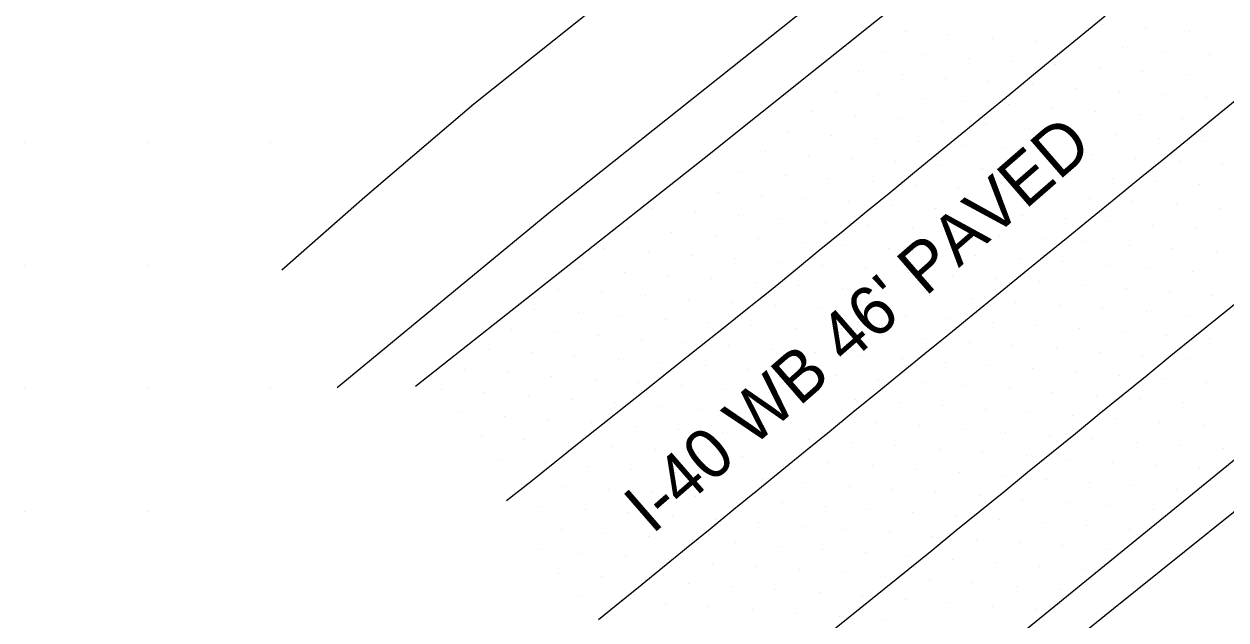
# Model space of a CAD drawing. Extents: x 1548934 to 1561348, y 809680 to 824075.
# Drawn here: x 1551360 to 1551457.5, y 810431.2 to 810479.5 of the extents above; entities that cross this region are included whole.
import ezdxf

# ---------------------------------------------------------------- set-up
doc = ezdxf.new("R2010")
doc.units = 0
for name, color, linetype in [('E_NCDOT_Vertical_Profile_Ground_Line', 7, 'Continuous'), ('Exist DTM QL2 LIDAR Elevation Point', 7, 'Continuous'), ('Exist DTM Scan Elevation Point', 7, 'Continuous'), ('Exist Roads EOP Text', 7, 'Continuous'), ('P_RDY_Terminator_Cell', 7, 'Continuous'), ('PH Exist DTM Breakline', 7, 'Continuous')]:
    doc.layers.add(name, color=color, linetype=linetype)

msp = doc.modelspace()

# ---------------------------------------------------------------- linework, layer by layer
at = {"layer": 'E_NCDOT_Vertical_Profile_Ground_Line'}
for points in [[(1551391.748, 810450.158), (1551415.179, 810468.674), (1551438.587, 810487.393), (1551461.862, 810506.256), (1551485.056, 810525.284), (1551508.262, 810544.296), (1551531.347, 810563.293), (1551554.369, 810582.488), (1551577.415, 810601.694), (1551600.296, 810621.053), (1551623.114, 810640.529), (1551645.931, 810660.005)], [(1551420.508, 810413.559), (1551431.924, 810422.797), (1551455.236, 810441.768), (1551478.523, 810460.78), (1551501.702, 810479.825), (1551524.839, 810499.022), (1551547.879, 810518.234), (1551570.873, 810537.502), (1551593.819, 810556.903), (1551616.71, 810576.292), (1551639.811, 810595.486)]]:
    msp.add_lwpolyline(points, dxfattribs=at)
at = {"layer": 'Exist DTM QL2 LIDAR Elevation Point'}
for p, q in [((1551359.968, 810469.969), (1551359.968, 810469.969)), ((1551369.969, 810469.969), (1551369.969, 810469.969)), ((1551379.969, 810469.969), (1551379.969, 810469.969)), ((1551359.968, 810459.968), (1551359.968, 810459.968)), ((1551369.969, 810459.968), (1551369.969, 810459.968)), ((1551359.968, 810449.967), (1551359.968, 810449.967)), ((1551369.969, 810449.967), (1551369.969, 810449.967)), ((1551379.969, 810449.967), (1551379.969, 810449.967)), ((1551359.968, 810439.966), (1551359.968, 810439.966)), ((1551369.969, 810439.966), (1551369.969, 810439.966))]:
    msp.add_line(p, q, dxfattribs=at)
at = {"layer": 'Exist DTM Scan Elevation Point'}
for p, q in [((1551431.502, 810478.948), (1551431.502, 810478.948)), ((1551447.498, 810479.506), (1551447.498, 810479.506)), ((1551451.024, 810479.238), (1551451.024, 810479.238)), ((1551454.549, 810478.97), (1551454.549, 810478.97)), ((1551435.027, 810478.68), (1551435.027, 810478.68)), ((1551438.552, 810478.412), (1551438.552, 810478.412)), ((1551442.077, 810478.144), (1551442.077, 810478.144)), ((1551445.602, 810477.877), (1551445.602, 810477.877)), ((1551429.606, 810477.319), (1551429.606, 810477.319)), ((1551433.131, 810477.051), (1551433.131, 810477.051)), ((1551436.656, 810476.783), (1551436.656, 810476.783)), ((1551449.127, 810477.609), (1551449.127, 810477.609)), ((1551452.652, 810477.341), (1551452.652, 810477.341)), ((1551456.178, 810477.074), (1551456.178, 810477.074)), ((1551440.181, 810476.516), (1551440.181, 810476.516)), ((1551443.706, 810476.248), (1551443.706, 810476.248)), ((1551447.231, 810475.98), (1551447.231, 810475.98)), ((1551427.71, 810475.69), (1551427.71, 810475.69)), ((1551431.235, 810475.422), (1551431.235, 810475.422)), ((1551434.759, 810475.155), (1551434.759, 810475.155)), ((1551438.284, 810474.887), (1551438.284, 810474.887)), ((1551450.756, 810475.713), (1551450.756, 810475.713)), ((1551454.281, 810475.445), (1551454.281, 810475.445)), ((1551425.813, 810474.062), (1551425.813, 810474.062)), ((1551441.809, 810474.619), (1551441.809, 810474.619)), ((1551445.334, 810474.351), (1551445.334, 810474.351)), ((1551448.86, 810474.084), (1551448.86, 810474.084)), ((1551452.385, 810473.816), (1551452.385, 810473.816)), ((1551429.338, 810473.794), (1551429.338, 810473.794)), ((1551432.863, 810473.526), (1551432.863, 810473.526)), ((1551436.388, 810473.258), (1551436.388, 810473.258)), ((1551439.913, 810472.99), (1551439.913, 810472.99)), ((1551455.91, 810473.548), (1551455.91, 810473.548)), ((1551423.917, 810472.433), (1551423.917, 810472.433)), ((1551427.442, 810472.165), (1551427.442, 810472.165)), ((1551430.967, 810471.897), (1551430.967, 810471.897)), ((1551443.438, 810472.722), (1551443.438, 810472.722)), ((1551446.963, 810472.455), (1551446.963, 810472.455)), ((1551450.489, 810472.187), (1551450.489, 810472.187)), ((1551454.014, 810471.92), (1551454.014, 810471.92)), ((1551434.492, 810471.629), (1551434.492, 810471.629)), ((1551438.017, 810471.361), (1551438.017, 810471.361)), ((1551441.542, 810471.093), (1551441.542, 810471.093)), ((1551422.021, 810470.804), (1551422.021, 810470.804)), ((1551425.545, 810470.536), (1551425.545, 810470.536)), ((1551429.07, 810470.268), (1551429.07, 810470.268)), ((1551432.595, 810470), (1551432.595, 810470)), ((1551445.067, 810470.826), (1551445.067, 810470.826)), ((1551448.592, 810470.558), (1551448.592, 810470.558)), ((1551452.117, 810470.291), (1551452.117, 810470.291)), ((1551455.643, 810470.023), (1551455.643, 810470.023)), ((1551420.124, 810469.175), (1551420.124, 810469.175)), ((1551436.12, 810469.732), (1551436.12, 810469.732)), ((1551439.645, 810469.464), (1551439.645, 810469.464)), ((1551443.171, 810469.197), (1551443.171, 810469.197)), ((1551423.649, 810468.907), (1551423.649, 810468.907)), ((1551427.174, 810468.639), (1551427.174, 810468.639)), ((1551430.699, 810468.371), (1551430.699, 810468.371)), ((1551434.224, 810468.103), (1551434.224, 810468.103)), ((1551446.696, 810468.929), (1551446.696, 810468.929)), ((1551450.221, 810468.662), (1551450.221, 810468.662)), ((1551453.746, 810468.394), (1551453.746, 810468.394)), ((1551457.272, 810468.126), (1551457.272, 810468.126)), ((1551418.228, 810467.546), (1551418.228, 810467.546)), ((1551421.752, 810467.278), (1551421.752, 810467.278)), ((1551425.277, 810467.01), (1551425.277, 810467.01)), ((1551437.749, 810467.836), (1551437.749, 810467.836)), ((1551441.274, 810467.568), (1551441.274, 810467.568)), ((1551444.799, 810467.3), (1551444.799, 810467.3)), ((1551448.325, 810467.033), (1551448.325, 810467.033)), ((1551428.802, 810466.742), (1551428.802, 810466.742)), ((1551432.327, 810466.474), (1551432.327, 810466.474)), ((1551435.853, 810466.207), (1551435.853, 810466.207)), ((1551451.85, 810466.765), (1551451.85, 810466.765)), ((1551455.375, 810466.497), (1551455.375, 810466.497)), ((1551416.331, 810465.917), (1551416.331, 810465.917)), ((1551419.856, 810465.649), (1551419.856, 810465.649)), ((1551423.381, 810465.381), (1551423.381, 810465.381)), ((1551426.906, 810465.113), (1551426.906, 810465.113)), ((1551439.378, 810465.939), (1551439.378, 810465.939)), ((1551442.903, 810465.671), (1551442.903, 810465.671)), ((1551446.428, 810465.404), (1551446.428, 810465.404)), ((1551449.954, 810465.136), (1551449.954, 810465.136)), ((1551410.91, 810464.556), (1551410.91, 810464.556)), ((1551414.435, 810464.288), (1551414.435, 810464.288)), ((1551430.431, 810464.845), (1551430.431, 810464.845)), ((1551433.956, 810464.578), (1551433.956, 810464.578)), ((1551437.481, 810464.31), (1551437.481, 810464.31)), ((1551453.479, 810464.869), (1551453.479, 810464.869)), ((1551457.004, 810464.601), (1551457.004, 810464.601)), ((1551417.96, 810464.02), (1551417.96, 810464.02)), ((1551421.485, 810463.752), (1551421.485, 810463.752)), ((1551425.01, 810463.484), (1551425.01, 810463.484)), ((1551428.535, 810463.216), (1551428.535, 810463.216)), ((1551441.007, 810464.042), (1551441.007, 810464.042)), ((1551444.532, 810463.775), (1551444.532, 810463.775)), ((1551448.057, 810463.507), (1551448.057, 810463.507)), ((1551451.582, 810463.24), (1551451.582, 810463.24)), ((1551409.014, 810462.927), (1551409.014, 810462.927)), ((1551412.538, 810462.659), (1551412.538, 810462.659)), ((1551416.063, 810462.391), (1551416.063, 810462.391)), ((1551419.588, 810462.123), (1551419.588, 810462.123)), ((1551432.06, 810462.949), (1551432.06, 810462.949)), ((1551435.585, 810462.681), (1551435.585, 810462.681)), ((1551439.11, 810462.414), (1551439.11, 810462.414)), ((1551442.636, 810462.146), (1551442.636, 810462.146)), ((1551455.107, 810462.972), (1551455.107, 810462.972)), ((1551407.117, 810461.298), (1551407.117, 810461.298)), ((1551423.113, 810461.855), (1551423.113, 810461.855)), ((1551426.638, 810461.587), (1551426.638, 810461.587)), ((1551430.163, 810461.32), (1551430.163, 810461.32)), ((1551446.161, 810461.878), (1551446.161, 810461.878)), ((1551449.686, 810461.611), (1551449.686, 810461.611)), ((1551453.211, 810461.343), (1551453.211, 810461.343)), ((1551410.642, 810461.03), (1551410.642, 810461.03)), ((1551414.167, 810460.762), (1551414.167, 810460.762)), ((1551417.692, 810460.494), (1551417.692, 810460.494)), ((1551421.217, 810460.226), (1551421.217, 810460.226)), ((1551433.689, 810461.052), (1551433.689, 810461.052)), ((1551437.214, 810460.785), (1551437.214, 810460.785)), ((1551440.739, 810460.517), (1551440.739, 810460.517)), ((1551444.264, 810460.249), (1551444.264, 810460.249)), ((1551456.736, 810461.075), (1551456.736, 810461.075)), ((1551405.22, 810459.668), (1551405.22, 810459.668)), ((1551408.745, 810459.401), (1551408.745, 810459.401)), ((1551424.742, 810459.959), (1551424.742, 810459.959)), ((1551428.267, 810459.691), (1551428.267, 810459.691)), ((1551431.792, 810459.423), (1551431.792, 810459.423)), ((1551447.789, 810459.982), (1551447.789, 810459.982)), ((1551451.315, 810459.714), (1551451.315, 810459.714)), ((1551454.84, 810459.446), (1551454.84, 810459.446)), ((1551412.27, 810459.133), (1551412.27, 810459.133)), ((1551415.795, 810458.865), (1551415.795, 810458.865)), ((1551419.32, 810458.597), (1551419.32, 810458.597)), ((1551422.845, 810458.33), (1551422.845, 810458.33)), ((1551435.318, 810459.156), (1551435.318, 810459.156)), ((1551438.843, 810458.888), (1551438.843, 810458.888)), ((1551442.368, 810458.62), (1551442.368, 810458.62)), ((1551445.893, 810458.353), (1551445.893, 810458.353)), ((1551403.323, 810458.039), (1551403.323, 810458.039)), ((1551406.848, 810457.771), (1551406.848, 810457.771)), ((1551410.374, 810457.504), (1551410.374, 810457.504)), ((1551413.899, 810457.236), (1551413.899, 810457.236)), ((1551426.371, 810458.062), (1551426.371, 810458.062)), ((1551429.896, 810457.794), (1551429.896, 810457.794)), ((1551433.421, 810457.527), (1551433.421, 810457.527)), ((1551436.946, 810457.259), (1551436.946, 810457.259)), ((1551449.418, 810458.085), (1551449.418, 810458.085)), ((1551452.943, 810457.817), (1551452.943, 810457.817)), ((1551456.469, 810457.55), (1551456.469, 810457.55)), ((1551401.427, 810456.411), (1551401.427, 810456.411)), ((1551417.424, 810456.968), (1551417.424, 810456.968)), ((1551420.949, 810456.701), (1551420.949, 810456.701)), ((1551424.474, 810456.433), (1551424.474, 810456.433)), ((1551440.472, 810456.991), (1551440.472, 810456.991)), ((1551443.997, 810456.724), (1551443.997, 810456.724)), ((1551447.522, 810456.456), (1551447.522, 810456.456)), ((1551404.952, 810456.142), (1551404.952, 810456.142)), ((1551408.477, 810455.875), (1551408.477, 810455.875)), ((1551412.002, 810455.607), (1551412.002, 810455.607)), ((1551415.528, 810455.34), (1551415.528, 810455.34)), ((1551428, 810456.165), (1551428, 810456.165)), ((1551431.525, 810455.898), (1551431.525, 810455.898)), ((1551435.05, 810455.63), (1551435.05, 810455.63)), ((1551438.575, 810455.363), (1551438.575, 810455.363)), ((1551451.047, 810456.189), (1551451.047, 810456.189)), ((1551454.572, 810455.921), (1551454.572, 810455.921)), ((1551399.531, 810454.781), (1551399.531, 810454.781)), ((1551403.056, 810454.514), (1551403.056, 810454.514)), ((1551419.053, 810455.072), (1551419.053, 810455.072)), ((1551422.578, 810454.804), (1551422.578, 810454.804)), ((1551426.103, 810454.536), (1551426.103, 810454.536)), ((1551442.1, 810455.095), (1551442.1, 810455.095)), ((1551445.625, 810454.827), (1551445.625, 810454.827)), ((1551449.151, 810454.56), (1551449.151, 810454.56)), ((1551406.581, 810454.246), (1551406.581, 810454.246)), ((1551410.106, 810453.978), (1551410.106, 810453.978)), ((1551413.631, 810453.71), (1551413.631, 810453.71)), ((1551417.156, 810453.443), (1551417.156, 810453.443)), ((1551429.628, 810454.269), (1551429.628, 810454.269)), ((1551433.154, 810454.001), (1551433.154, 810454.001)), ((1551436.679, 810453.734), (1551436.679, 810453.734)), ((1551440.204, 810453.466), (1551440.204, 810453.466)), ((1551452.676, 810454.292), (1551452.676, 810454.292)), ((1551456.202, 810454.025), (1551456.202, 810454.025)), ((1551397.635, 810453.153), (1551397.635, 810453.153)), ((1551401.159, 810452.885), (1551401.159, 810452.885)), ((1551404.685, 810452.617), (1551404.685, 810452.617)), ((1551408.209, 810452.349), (1551408.209, 810452.349)), ((1551420.682, 810453.175), (1551420.682, 810453.175)), ((1551424.207, 810452.908), (1551424.207, 810452.908)), ((1551427.732, 810452.64), (1551427.732, 810452.64)), ((1551431.257, 810452.372), (1551431.257, 810452.372)), ((1551443.729, 810453.198), (1551443.729, 810453.198)), ((1551447.254, 810452.931), (1551447.254, 810452.931)), ((1551450.78, 810452.663), (1551450.78, 810452.663)), ((1551454.305, 810452.396), (1551454.305, 810452.396)), ((1551395.738, 810451.523), (1551395.738, 810451.523)), ((1551411.735, 810452.081), (1551411.735, 810452.081)), ((1551415.26, 810451.814), (1551415.26, 810451.814)), ((1551418.785, 810451.546), (1551418.785, 810451.546)), ((1551434.782, 810452.105), (1551434.782, 810452.105)), ((1551438.308, 810451.837), (1551438.308, 810451.837)), ((1551441.833, 810451.569), (1551441.833, 810451.569)), ((1551399.263, 810451.256), (1551399.263, 810451.256)), ((1551402.788, 810450.988), (1551402.788, 810450.988)), ((1551406.313, 810450.72), (1551406.313, 810450.72)), ((1551409.838, 810450.452), (1551409.838, 810450.452)), ((1551422.31, 810451.279), (1551422.31, 810451.279)), ((1551425.836, 810451.011), (1551425.836, 810451.011)), ((1551429.361, 810450.743), (1551429.361, 810450.743)), ((1551432.886, 810450.476), (1551432.886, 810450.476)), ((1551445.358, 810451.302), (1551445.358, 810451.302)), ((1551448.883, 810451.034), (1551448.883, 810451.034)), ((1551452.409, 810450.767), (1551452.409, 810450.767)), ((1551455.935, 810450.5), (1551455.935, 810450.5)), ((1551393.842, 810449.894), (1551393.842, 810449.894)), ((1551397.366, 810449.626), (1551397.366, 810449.626)), ((1551413.363, 810450.185), (1551413.363, 810450.185)), ((1551416.889, 810449.917), (1551416.889, 810449.917)), ((1551420.414, 810449.65), (1551420.414, 810449.65)), ((1551436.411, 810450.208), (1551436.411, 810450.208)), ((1551439.936, 810449.94), (1551439.936, 810449.94)), ((1551443.462, 810449.673), (1551443.462, 810449.673)), ((1551400.892, 810449.359), (1551400.892, 810449.359)), ((1551404.417, 810449.091), (1551404.417, 810449.091)), ((1551407.942, 810448.824), (1551407.942, 810448.824)), ((1551411.467, 810448.556), (1551411.467, 810448.556)), ((1551423.939, 810449.382), (1551423.939, 810449.382)), ((1551427.464, 810449.114), (1551427.464, 810449.114)), ((1551430.99, 810448.847), (1551430.99, 810448.847)), ((1551434.515, 810448.579), (1551434.515, 810448.579)), ((1551446.987, 810449.405), (1551446.987, 810449.405)), ((1551450.513, 810449.138), (1551450.513, 810449.138)), ((1551454.038, 810448.871), (1551454.038, 810448.871)), ((1551395.47, 810447.998), (1551395.47, 810447.998)), ((1551398.995, 810447.73), (1551398.995, 810447.73)), ((1551414.992, 810448.288), (1551414.992, 810448.288)), ((1551418.518, 810448.021), (1551418.518, 810448.021)), ((1551422.043, 810447.753), (1551422.043, 810447.753)), ((1551425.568, 810447.486), (1551425.568, 810447.486)), ((1551438.04, 810448.311), (1551438.04, 810448.311)), ((1551441.565, 810448.044), (1551441.565, 810448.044)), ((1551445.09, 810447.776), (1551445.09, 810447.776)), ((1551448.616, 810447.509), (1551448.616, 810447.509)), ((1551402.521, 810447.462), (1551402.521, 810447.462)), ((1551406.046, 810447.195), (1551406.046, 810447.195)), ((1551409.571, 810446.927), (1551409.571, 810446.927)), ((1551413.096, 810446.659), (1551413.096, 810446.659)), ((1551429.093, 810447.218), (1551429.093, 810447.218)), ((1551432.618, 810446.95), (1551432.618, 810446.95)), ((1551436.143, 810446.682), (1551436.143, 810446.682)), ((1551452.142, 810447.242), (1551452.142, 810447.242)), ((1551455.668, 810446.975), (1551455.668, 810446.975)), ((1551397.099, 810446.101), (1551397.099, 810446.101)), ((1551400.624, 810445.833), (1551400.624, 810445.833)), ((1551404.149, 810445.566), (1551404.149, 810445.566)), ((1551416.621, 810446.392), (1551416.621, 810446.392)), ((1551420.146, 810446.124), (1551420.146, 810446.124)), ((1551423.672, 810445.857), (1551423.672, 810445.857)), ((1551427.197, 810445.589), (1551427.197, 810445.589)), ((1551439.669, 810446.415), (1551439.669, 810446.415)), ((1551443.194, 810446.147), (1551443.194, 810446.147)), ((1551446.72, 810445.88), (1551446.72, 810445.88)), ((1551450.245, 810445.613), (1551450.245, 810445.613)), ((1551407.674, 810445.298), (1551407.674, 810445.298)), ((1551411.199, 810445.03), (1551411.199, 810445.03)), ((1551414.725, 810444.763), (1551414.725, 810444.763)), ((1551430.722, 810445.321), (1551430.722, 810445.321)), ((1551434.247, 810445.054), (1551434.247, 810445.054)), ((1551437.772, 810444.786), (1551437.772, 810444.786)), ((1551453.771, 810445.346), (1551453.771, 810445.346)), ((1551457.297, 810445.079), (1551457.297, 810445.079)), ((1551398.728, 810444.204), (1551398.728, 810444.204)), ((1551402.253, 810443.937), (1551402.253, 810443.937)), ((1551405.778, 810443.669), (1551405.778, 810443.669)), ((1551418.25, 810444.495), (1551418.25, 810444.495)), ((1551421.775, 810444.228), (1551421.775, 810444.228)), ((1551425.3, 810443.96), (1551425.3, 810443.96)), ((1551428.826, 810443.692), (1551428.826, 810443.692)), ((1551441.298, 810444.518), (1551441.298, 810444.518)), ((1551444.823, 810444.251), (1551444.823, 810444.251)), ((1551448.349, 810443.984), (1551448.349, 810443.984)), ((1551451.875, 810443.717), (1551451.875, 810443.717)), ((1551409.303, 810443.401), (1551409.303, 810443.401)), ((1551412.828, 810443.134), (1551412.828, 810443.134)), ((1551416.354, 810442.866), (1551416.354, 810442.866)), ((1551419.879, 810442.599), (1551419.879, 810442.599)), ((1551432.351, 810443.425), (1551432.351, 810443.425)), ((1551435.876, 810443.157), (1551435.876, 810443.157)), ((1551439.401, 810442.889), (1551439.401, 810442.889)), ((1551442.927, 810442.622), (1551442.927, 810442.622)), ((1551455.401, 810443.45), (1551455.401, 810443.45)), ((1551400.356, 810442.308), (1551400.356, 810442.308)), ((1551403.881, 810442.04), (1551403.881, 810442.04)), ((1551407.407, 810441.773), (1551407.407, 810441.773)), ((1551423.404, 810442.331), (1551423.404, 810442.331)), ((1551426.929, 810442.063), (1551426.929, 810442.063)), ((1551430.454, 810441.796), (1551430.454, 810441.796)), ((1551446.453, 810442.355), (1551446.453, 810442.355)), ((1551449.978, 810442.088), (1551449.978, 810442.088)), ((1551453.504, 810441.821), (1551453.504, 810441.821)), ((1551410.932, 810441.505), (1551410.932, 810441.505)), ((1551414.457, 810441.237), (1551414.457, 810441.237)), ((1551417.982, 810440.97), (1551417.982, 810440.97)), ((1551421.508, 810440.702), (1551421.508, 810440.702)), ((1551433.98, 810441.528), (1551433.98, 810441.528)), ((1551437.505, 810441.261), (1551437.505, 810441.261)), ((1551441.031, 810440.993), (1551441.031, 810440.993)), ((1551444.556, 810440.726), (1551444.556, 810440.726)), ((1551401.985, 810440.411), (1551401.985, 810440.411)), ((1551405.51, 810440.143), (1551405.51, 810440.143)), ((1551409.036, 810439.876), (1551409.036, 810439.876)), ((1551425.033, 810440.434), (1551425.033, 810440.434)), ((1551428.558, 810440.167), (1551428.558, 810440.167)), ((1551432.083, 810439.899), (1551432.083, 810439.899)), ((1551448.082, 810440.459), (1551448.082, 810440.459)), ((1551451.608, 810440.192), (1551451.608, 810440.192)), ((1551412.561, 810439.608), (1551412.561, 810439.608)), ((1551416.086, 810439.341), (1551416.086, 810439.341)), ((1551419.611, 810439.073), (1551419.611, 810439.073)), ((1551423.137, 810438.806), (1551423.137, 810438.806)), ((1551435.609, 810439.632), (1551435.609, 810439.632)), ((1551439.134, 810439.364), (1551439.134, 810439.364)), ((1551442.66, 810439.097), (1551442.66, 810439.097)), ((1551446.186, 810438.83), (1551446.186, 810438.83)), ((1551403.614, 810438.515), (1551403.614, 810438.515)), ((1551407.139, 810438.247), (1551407.139, 810438.247)), ((1551410.664, 810437.979), (1551410.664, 810437.979)), ((1551426.662, 810438.538), (1551426.662, 810438.538)), ((1551430.187, 810438.27), (1551430.187, 810438.27)), ((1551433.712, 810438.003), (1551433.712, 810438.003)), ((1551437.238, 810437.736), (1551437.238, 810437.736)), ((1551449.712, 810438.563), (1551449.712, 810438.563)), ((1551401.718, 810436.886), (1551401.718, 810436.886)), ((1551414.19, 810437.712), (1551414.19, 810437.712)), ((1551417.715, 810437.444), (1551417.715, 810437.444)), ((1551421.24, 810437.177), (1551421.24, 810437.177)), ((1551424.765, 810436.909), (1551424.765, 810436.909)), ((1551440.763, 810437.468), (1551440.763, 810437.468)), ((1551444.289, 810437.201), (1551444.289, 810437.201)), ((1551447.815, 810436.934), (1551447.815, 810436.934)), ((1551405.243, 810436.618), (1551405.243, 810436.618)), ((1551408.768, 810436.35), (1551408.768, 810436.35)), ((1551412.293, 810436.083), (1551412.293, 810436.083)), ((1551415.818, 810435.815), (1551415.818, 810435.815)), ((1551428.291, 810436.641), (1551428.291, 810436.641)), ((1551431.816, 810436.374), (1551431.816, 810436.374)), ((1551435.341, 810436.107), (1551435.341, 810436.107)), ((1551438.867, 810435.839), (1551438.867, 810435.839)), ((1551403.346, 810434.989), (1551403.346, 810434.989)), ((1551419.344, 810435.548), (1551419.344, 810435.548)), ((1551422.869, 810435.28), (1551422.869, 810435.28)), ((1551426.394, 810435.013), (1551426.394, 810435.013)), ((1551442.393, 810435.572), (1551442.393, 810435.572)), ((1551445.919, 810435.305), (1551445.919, 810435.305)), ((1551406.872, 810434.722), (1551406.872, 810434.722)), ((1551410.397, 810434.454), (1551410.397, 810434.454)), ((1551413.922, 810434.186), (1551413.922, 810434.186)), ((1551417.447, 810433.919), (1551417.447, 810433.919)), ((1551429.92, 810434.745), (1551429.92, 810434.745)), ((1551433.445, 810434.478), (1551433.445, 810434.478)), ((1551436.971, 810434.21), (1551436.971, 810434.21)), ((1551440.496, 810433.943), (1551440.496, 810433.943)), ((1551404.975, 810433.093), (1551404.975, 810433.093)), ((1551420.973, 810433.651), (1551420.973, 810433.651)), ((1551424.498, 810433.384), (1551424.498, 810433.384)), ((1551428.023, 810433.116), (1551428.023, 810433.116)), ((1551431.549, 810432.849), (1551431.549, 810432.849)), ((1551444.022, 810433.676), (1551444.022, 810433.676)), ((1551408.5, 810432.825), (1551408.5, 810432.825)), ((1551412.026, 810432.557), (1551412.026, 810432.557)), ((1551415.551, 810432.29), (1551415.551, 810432.29)), ((1551419.076, 810432.022), (1551419.076, 810432.022)), ((1551435.074, 810432.581), (1551435.074, 810432.581)), ((1551438.6, 810432.314), (1551438.6, 810432.314)), ((1551442.126, 810432.047), (1551442.126, 810432.047)), ((1551422.601, 810431.755), (1551422.601, 810431.755)), ((1551426.127, 810431.487), (1551426.127, 810431.487)), ((1551429.652, 810431.22), (1551429.652, 810431.22))]:
    msp.add_line(p, q, dxfattribs=at)
at = {"layer": 'P_RDY_Terminator_Cell'}
for points in [[(1551399.137, 810440.884), (1551401.093, 810442.442), (1551403.048, 810444), (1551405.003, 810445.558), (1551406.958, 810447.116), (1551408.914, 810448.674), (1551410.869, 810450.232), (1551412.824, 810451.79), (1551414.779, 810453.347), (1551416.734, 810454.905), (1551418.69, 810456.463), (1551420.645, 810458.021), (1551422.582, 810459.601), (1551424.515, 810461.187), (1551426.448, 810462.772), (1551428.381, 810464.357), (1551430.315, 810465.942), (1551432.248, 810467.528), (1551434.181, 810469.113), (1551436.114, 810470.698), (1551438.047, 810472.284), (1551439.98, 810473.869), (1551441.913, 810475.454), (1551443.846, 810477.039), (1551445.779, 810478.625), (1551447.713, 810480.21)], [(1551458.282, 810473.323), (1551456.344, 810471.743), (1551454.406, 810470.163), (1551452.468, 810468.584), (1551450.531, 810467.004), (1551448.593, 810465.424), (1551446.655, 810463.845), (1551444.717, 810462.265), (1551442.78, 810460.686), (1551440.842, 810459.106), (1551438.904, 810457.526), (1551436.966, 810455.947), (1551435.029, 810454.367), (1551433.091, 810452.788), (1551431.153, 810451.208), (1551429.215, 810449.628), (1551427.278, 810448.049), (1551425.34, 810446.469), (1551423.402, 810444.89), (1551421.464, 810443.31), (1551419.527, 810441.73), (1551417.589, 810440.151), (1551415.651, 810438.571), (1551413.713, 810436.992), (1551411.776, 810435.412), (1551409.838, 810433.832), (1551407.9, 810432.253), (1551406.604, 810431.196)], [(1551458.895, 810457.328), (1551456.949, 810455.758), (1551455.002, 810454.189), (1551453.057, 810452.619), (1551451.118, 810451.041), (1551449.179, 810449.463), (1551447.239, 810447.886), (1551445.3, 810446.308), (1551443.361, 810444.73), (1551441.421, 810443.153), (1551439.482, 810441.575), (1551437.543, 810439.997), (1551435.604, 810438.42), (1551433.664, 810436.842), (1551431.725, 810435.264), (1551429.776, 810433.698), (1551427.828, 810432.131), (1551425.88, 810430.565), (1551423.931, 810428.998), (1551421.983, 810427.432), (1551420.035, 810425.865), (1551418.086, 810424.299), (1551416.138, 810422.732), (1551414.313, 810421.265)]]:
    msp.add_lwpolyline(points, dxfattribs=at)
at = {"layer": 'PH Exist DTM Breakline'}
for points in [[(1551623.76, 810648.551), (1551611.653, 810637.657), (1551598.616, 810624.306), (1551581.601, 810609.451), (1551566.315, 810596.609), (1551550.141, 810583.072), (1551531.518, 810567.498), (1551514.04, 810553.206), (1551494.6, 810537.72), (1551475.139, 810521.964), (1551457.515, 810507.591), (1551444.994, 810497.86), (1551424.723, 810481.845), (1551402.559, 810464.194), (1551385.382, 810450.038)], [(1551417.883, 810407.398), (1551432.392, 810419.235), (1551448.388, 810432.126), (1551463.908, 810444.556), (1551480.556, 810458.727), (1551495.998, 810470.721), (1551512.779, 810483.455), (1551526.124, 810494.877), (1551540.797, 810506.743), (1551554.488, 810518.26), (1551567.602, 810529.513), (1551583.151, 810542.273), (1551597.076, 810551.659), (1551607.705, 810560.571), (1551621.142, 810571.735), (1551639.856, 810587.953), (1551647.753, 810594.047)], [(1551472.816, 810536.626), (1551461.263, 810527.531), (1551456.359, 810524.212), (1551453.12, 810520.059), (1551449.257, 810516.353), (1551443.324, 810511.997), (1551433.862, 810503.327), (1551425.421, 810496.447), (1551415.743, 810488.136), (1551406.33, 810480.881), (1551396.486, 810473.035), (1551387.642, 810465.488), (1551380.891, 810459.589)]]:
    msp.add_lwpolyline(points, dxfattribs=at)

# ---------------------------------------------------------------- texts
at = {"layer": 'Exist Roads EOP Text'}
msp.add_text("I-40 WB 46' PAVED", height=4.02, rotation=41.03095, dxfattribs=at).set_placement((1551410.942, 810438.076))

doc.saveas('drawing.dxf')
